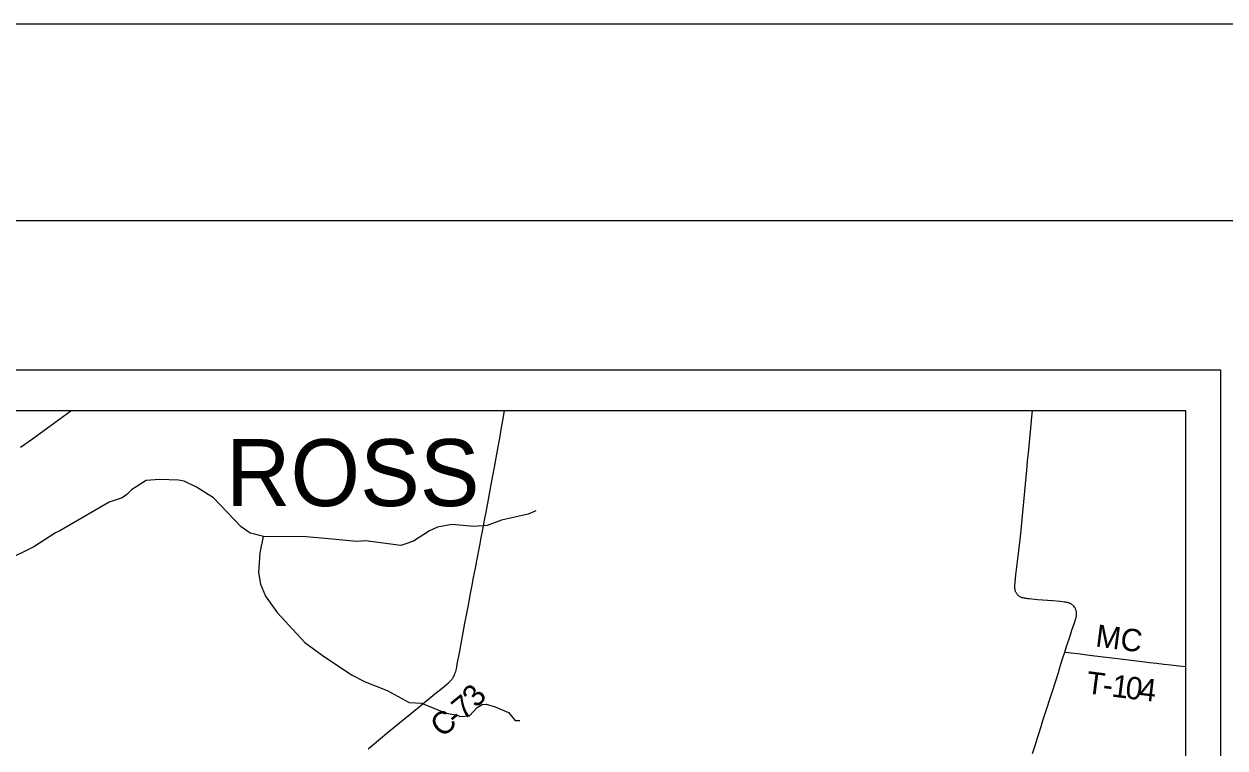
# Model space of a CAD drawing. Extents: x -5.4 to 49.9, y 13.2 to 48.4.
# Drawn here: x 30.118 to 33.177, y 46.585 to 48.429 of the extents above; entities that cross this region are included whole.
import ezdxf

# ---------------------------------------------------------------- set-up
doc = ezdxf.new("R2010")
doc.units = 0
for name, color, linetype in [('GM_X_County_Road', 7, 'Continuous'), ('GM_X_County_Road_Text', 7, 'Continuous'), ('GM_X_Minor_River', 7, 'Continuous'), ('GM_X_Township', 7, 'Continuous'), ('GM_X_Township_Road', 7, 'Continuous'), ('GM_X_Township_Road_Text', 7, 'Continuous'), ('GM_X_Township_Text', 7, 'Continuous'), ('SH_Border', 7, 'Continuous'), ('SH_Cut_Line', 7, 'Continuous'), ('SH_Data', 7, 'Continuous')]:
    doc.layers.add(name, color=color, linetype=linetype)

msp = doc.modelspace()

# ---------------------------------------------------------------- linework, layer by layer
at = {"layer": 'GM_X_County_Road'}
for points in [[(30.1093, 47.351), (30.1397, 47.3727), (30.1591, 47.3871), (30.1934, 47.4118), (30.2373, 47.4437)], [(30.9941, 46.5831), (31.0471, 46.6271), (31.088, 46.6606), (31.1241, 46.6901), (31.1645, 46.7231), (31.1829, 46.7379), (31.1886, 46.7426), (31.1939, 46.747), (31.2001, 46.7522), (31.2024, 46.7545), (31.2053, 46.7574), (31.2073, 46.7597), (31.2087, 46.7615), (31.2101, 46.7635), (31.2118, 46.7662), (31.2132, 46.7687), (31.2142, 46.7709), (31.2155, 46.7739), (31.2165, 46.7769), (31.2175, 46.7803), (31.2184, 46.7837), (31.2193, 46.7868), (31.2202, 46.791), (31.2216, 46.7984), (31.227, 46.8277), (31.2328, 46.8595), (31.2409, 46.9035), (31.244, 46.9194), (31.2489, 46.945), (31.2553, 46.9786), (31.2594, 46.9999), (31.2631, 47.0194), (31.2676, 47.0433), (31.2712, 47.0622), (31.2788, 47.1013), (31.2825, 47.1201), (31.2881, 47.15), (31.2904, 47.1616), (31.2948, 47.1856), (31.301, 47.2184), (31.3081, 47.2561), (31.3165, 47.3008), (31.3241, 47.343), (31.3305, 47.3791), (31.3336, 47.3962), (31.3375, 47.4195), (31.3415, 47.4437)]]:
    msp.add_lwpolyline(points, dxfattribs=at)
at = {"layer": 'GM_X_Minor_River'}
for points in [[(31.4214, 47.189), (31.4019, 47.1806), (31.3338, 47.1652), (31.2976, 47.1518), (31.2638, 47.149), (31.2078, 47.1542), (31.1713, 47.1476), (31.1511, 47.1385), (31.1104, 47.1119), (31.0879, 47.104), (31.0777, 47.1011), (30.988, 47.1127), (30.966, 47.1112), (30.9025, 47.1173), (30.8272, 47.1236), (30.7317, 47.1231), (30.7181, 47.126), (30.7056, 47.1296), (30.6939, 47.1321), (30.6707, 47.1481), (30.6004, 47.222), (30.5573, 47.2493), (30.5258, 47.2644), (30.511, 47.2677), (30.4629, 47.2693), (30.4292, 47.2665), (30.3916, 47.2429), (30.3796, 47.2309), (30.3681, 47.2224), (30.3349, 47.2109), (30.209, 47.1387), (30.1979, 47.1329), (30.1427, 47.0978), (30.0704, 47.0615)], [(30.7271, 47.124), (30.7188, 47.0823), (30.7153, 47.0318), (30.72, 47.0021), (30.7332, 46.9719), (30.7631, 46.9303), (30.833, 46.8542), (30.8775, 46.8214), (30.9524, 46.7714), (30.9866, 46.7541), (31.0427, 46.7314), (31.0986, 46.7011), (31.13, 46.6998), (31.1928, 46.6743), (31.2185, 46.67), (31.2298, 46.6656), (31.2526, 46.6675), (31.2723, 46.6888), (31.2849, 46.6962), (31.2948, 46.6967), (31.3178, 46.6902), (31.3517, 46.6755), (31.3687, 46.6555), (31.3809, 46.6553)]]:
    msp.add_lwpolyline(points, dxfattribs=at)
at = {"layer": 'GM_X_Township'}
msp.add_lwpolyline([(33.0771, 44.431), (33.0771, 47.4437), (28.0105, 47.4437)], dxfattribs=at)
at = {"layer": 'GM_X_Township_Road'}
for points in [[(32.7689, 46.8296), (32.7726, 46.8414), (32.7833, 46.8739), (32.7872, 46.8857), (32.7936, 46.9039), (32.7963, 46.9121), (32.7971, 46.9148), (32.7976, 46.9169), (32.7981, 46.9193), (32.7984, 46.9208), (32.7987, 46.9224), (32.7989, 46.9249), (32.799, 46.9263), (32.7989, 46.9281), (32.7988, 46.9298), (32.7986, 46.9313), (32.7984, 46.9326), (32.7982, 46.9342), (32.7978, 46.9358), (32.7973, 46.9371), (32.7965, 46.9392), (32.796, 46.9406), (32.7952, 46.9421), (32.7944, 46.9433), (32.7937, 46.9443), (32.7922, 46.9462), (32.7909, 46.9476), (32.7899, 46.9485), (32.7889, 46.9494), (32.7879, 46.9501), (32.7869, 46.9508), (32.7858, 46.9515), (32.7842, 46.9524), (32.7828, 46.9531), (32.7814, 46.9538), (32.7801, 46.9543), (32.7787, 46.9548), (32.7769, 46.9554), (32.7752, 46.9559), (32.7737, 46.9562), (32.7715, 46.9566), (32.7686, 46.957), (32.7572, 46.9581), (32.7374, 46.9598), (32.6997, 46.963), (32.6781, 46.9651), (32.6745, 46.9654), (32.6723, 46.9657), (32.6698, 46.966), (32.6669, 46.9665), (32.6651, 46.9669), (32.6633, 46.9673), (32.6607, 46.9681), (32.6586, 46.9689), (32.6565, 46.9698), (32.6552, 46.9706), (32.6538, 46.9714), (32.6526, 46.9722), (32.651, 46.9734), (32.6497, 46.9745), (32.6485, 46.9757), (32.6476, 46.9768), (32.6466, 46.978), (32.6457, 46.9792), (32.6447, 46.981), (32.644, 46.9825), (32.6435, 46.9837), (32.6431, 46.9848), (32.6427, 46.9862), (32.6424, 46.9877), (32.6422, 46.9891), (32.6419, 46.9911), (32.6418, 46.9928), (32.6417, 46.9949), (32.6417, 46.9966), (32.6417, 46.999), (32.6419, 47.0023), (32.6421, 47.0044), (32.6423, 47.0065), (32.6446, 47.0262), (32.6477, 47.0534), (32.65, 47.0738), (32.6549, 47.1163), (32.6574, 47.1398), (32.661, 47.1763), (32.6643, 47.2122), (32.6686, 47.2573), (32.672, 47.2932), (32.6741, 47.3155), (32.6761, 47.3359), (32.6798, 47.3723), (32.6834, 47.4088), (32.6853, 47.4286), (32.6869, 47.4437)], [(32.6867, 46.5717), (32.6931, 46.5917), (32.6995, 46.6111), (32.7036, 46.624), (32.7078, 46.6377), (32.7134, 46.6554), (32.7255, 46.6932), (32.7291, 46.7045), (32.7382, 46.7328), (32.7525, 46.7778), (32.7583, 46.7962), (32.7643, 46.8151), (32.7689, 46.8296)], [(32.7689, 46.8296), (32.7934, 46.8267), (32.8078, 46.8249), (32.8316, 46.8219), (32.8667, 46.8176), (32.8821, 46.8157), (32.9105, 46.8121), (32.945, 46.8078), (32.966, 46.8053), (32.9845, 46.8034), (33.0024, 46.8013), (33.0215, 46.799), (33.0388, 46.7971), (33.0593, 46.7947), (33.0771, 46.7926)]]:
    msp.add_lwpolyline(points, dxfattribs=at)
at = {"layer": 'SH_Border'}
msp.add_lwpolyline([(4.2889, 47.9288), (36.2889, 47.9288), (36.2889, 26.9288), (4.2889, 26.9288)], close=True, dxfattribs=at)
at = {"layer": 'SH_Cut_Line'}
msp.add_lwpolyline([(2.7889, 26.4288), (36.7889, 26.4288), (36.7889, 48.4288), (2.7889, 48.4288)], close=True, dxfattribs=at)
at = {"layer": 'SH_Data'}
for p, q in [((26.1653, 47.5483), (33.1653, 47.5483)), ((33.1653, 47.5483), (33.1653, 40.5483))]:
    msp.add_line(p, q, dxfattribs=at)

# ---------------------------------------------------------------- texts
at = {"layer": 'GM_X_County_Road_Text'}
for s, rotation, p in [('3', 50.5743, (31.2723, 46.6852)), ('7', 39.4159, (31.2367, 46.6544)), ('C', 39.1584, (31.1822, 46.6101)), ('-', 39.1877, (31.2184, 46.6395))]:
    msp.add_text(s, height=0.0568, rotation=rotation, dxfattribs=at).set_placement(p)
at = {"layer": 'GM_X_Township_Road_Text'}
for s, height, rotation, p in [('MC', 0.05682, 352.6086, (32.8452, 46.8439)), ('T', 0.0568, 352.7596, (32.821, 46.7248)), ('-', 0.0568, 352.7675, (32.8632, 46.7194)), ('1', 0.0568, 352.8072, (32.8863, 46.7165)), ('0', 0.0568, 352.9646, (32.9212, 46.7121)), ('4', 0.0568, 353.6573, (32.9567, 46.7077))]:
    msp.add_text(s, height=height, rotation=rotation, dxfattribs=at).set_placement(p)
at = {"layer": 'GM_X_Township_Text'}
msp.add_text('ROSS', height=0.17045, rotation=0, dxfattribs=at).set_placement((30.6321, 47.2013))

doc.saveas('drawing.dxf')
